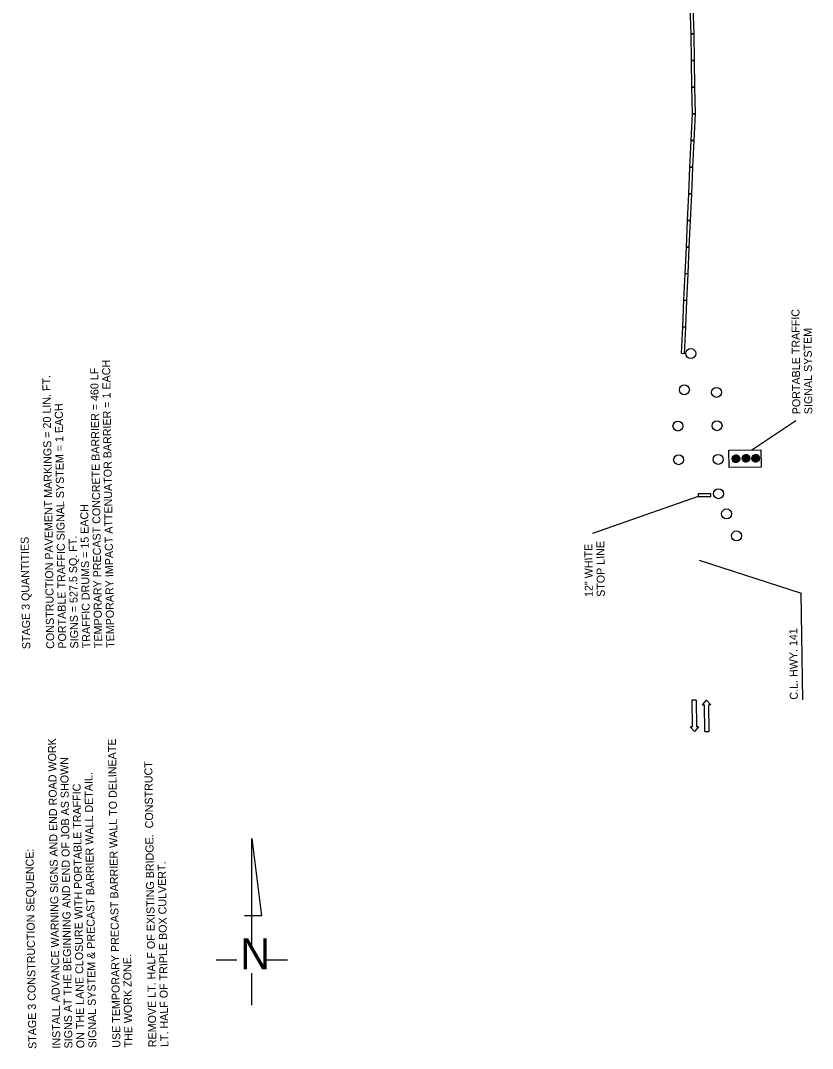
# Model space of a CAD drawing. Extents: x 1770269 to 1771406, y 724066 to 730989.
# Drawn here: x 1770318 to 1770912, y 724066 to 724837 of the extents above; entities that cross this region are included whole.
import ezdxf

# ---------------------------------------------------------------- set-up
doc = ezdxf.new("R2010")
doc.units = 0
for name, color, linetype in [('Default', 7, 'Continuous'), ('R_Border Notes', 7, 'Continuous'), ('R_Dimension', 7, 'Continuous'), ('R_Draft', 7, 'Continuous'), ('R_Horz Alg Annot', 7, 'Continuous'), ('R_MOT', 7, 'Continuous'), ('R_Striping', 7, 'Continuous'), ('T_Vehicle Path Rt', 7, 'Continuous')]:
    doc.layers.add(name, color=color, linetype=linetype)

msp = doc.modelspace()

# ---------------------------------------------------------------- linework, layer by layer
at = {"layer": 'Default'}
for p, q in [((1770854.8, 724505.27), (1770851.77, 724508.24)), ((1770854.63, 724505.26), (1770851.77, 724508.07)), ((1770854.97, 724505.28), (1770851.78, 724508.41)), ((1770854.44, 724505.27), (1770851.78, 724507.88)), ((1770855.12, 724505.3), (1770851.8, 724508.56)), ((1770854.24, 724505.29), (1770851.81, 724507.68)), ((1770855.27, 724505.33), (1770851.83, 724508.71)), ((1770854.02, 724505.33), (1770851.85, 724507.47)), ((1770855.41, 724505.37), (1770851.86, 724508.86)), ((1770855.55, 724505.41), (1770851.9, 724508.99)), ((1770853.78, 724505.39), (1770851.92, 724507.22)), ((1770855.68, 724505.45), (1770851.95, 724509.12)), ((1770855.81, 724505.51), (1770851.99, 724509.25)), ((1770853.49, 724505.5), (1770852.03, 724506.94)), ((1770855.93, 724505.56), (1770852.05, 724509.37)), ((1770856.04, 724505.62), (1770852.11, 724509.49)), ((1770856.15, 724505.69), (1770852.17, 724509.6)), ((1770856.26, 724505.76), (1770852.24, 724509.71)), ((1770853.1, 724505.71), (1770852.25, 724506.55)), ((1770856.37, 724505.83), (1770852.31, 724509.82)), ((1770856.46, 724505.91), (1770852.39, 724509.92)), ((1770856.56, 724505.99), (1770852.47, 724510.01)), ((1770856.65, 724506.08), (1770852.55, 724510.11)), ((1770856.74, 724506.17), (1770852.64, 724510.2)), ((1770856.82, 724506.26), (1770852.73, 724510.28)), ((1770856.9, 724506.36), (1770852.83, 724510.36)), ((1770856.98, 724506.46), (1770852.93, 724510.44)), ((1770857.05, 724506.56), (1770853.03, 724510.51)), ((1770857.12, 724506.67), (1770853.14, 724510.58)), ((1770857.18, 724506.78), (1770853.25, 724510.65)), ((1770857.24, 724506.9), (1770853.36, 724510.71)), ((1770857.3, 724507.02), (1770853.48, 724510.77)), ((1770857.34, 724507.15), (1770853.61, 724510.82)), ((1770857.39, 724507.28), (1770853.74, 724510.87)), ((1770857.43, 724507.42), (1770853.88, 724510.91)), ((1770857.46, 724507.56), (1770854.02, 724510.94)), ((1770857.49, 724507.71), (1770854.17, 724510.97)), ((1770857.51, 724507.87), (1770854.32, 724510.99)), ((1770857.52, 724508.03), (1770854.49, 724511.01)), ((1770857.52, 724508.2), (1770854.66, 724511.01)), ((1770857.51, 724508.39), (1770854.85, 724511)), ((1770857.48, 724508.59), (1770855.05, 724510.98)), ((1770857.44, 724508.81), (1770855.27, 724510.94)), ((1770857.37, 724509.05), (1770855.51, 724510.88)), ((1770857.26, 724509.34), (1770855.8, 724510.77)), ((1770857.04, 724509.73), (1770856.19, 724510.56)), ((1770862.29, 724505.6), (1770859.25, 724508.57)), ((1770862.11, 724505.59), (1770859.25, 724508.4)), ((1770861.93, 724505.6), (1770859.26, 724508.21)), ((1770862.45, 724505.61), (1770859.27, 724508.74)), ((1770862.61, 724505.63), (1770859.28, 724508.89)), ((1770861.73, 724505.62), (1770859.29, 724508.01)), ((1770862.75, 724505.66), (1770859.31, 724509.04)), ((1770861.51, 724505.66), (1770859.33, 724507.8)), ((1770862.9, 724505.7), (1770859.34, 724509.19)), ((1770863.03, 724505.74), (1770859.38, 724509.32)), ((1770861.26, 724505.72), (1770859.4, 724507.55)), ((1770863.16, 724505.78), (1770859.43, 724509.45)), ((1770863.29, 724505.84), (1770859.48, 724509.58)), ((1770860.97, 724505.83), (1770859.52, 724507.27)), ((1770863.41, 724505.89), (1770859.53, 724509.7)), ((1770863.53, 724505.95), (1770859.59, 724509.82)), ((1770863.64, 724506.02), (1770859.65, 724509.93)), ((1770863.74, 724506.09), (1770859.72, 724510.04)), ((1770860.58, 724506.04), (1770859.73, 724506.88)), ((1770863.85, 724506.16), (1770859.79, 724510.15)), ((1770863.95, 724506.24), (1770859.87, 724510.25)), ((1770864.04, 724506.32), (1770859.95, 724510.34)), ((1770864.13, 724506.41), (1770860.03, 724510.44)), ((1770864.22, 724506.5), (1770860.12, 724510.52)), ((1770864.31, 724506.59), (1770860.21, 724510.61)), ((1770864.39, 724506.69), (1770860.31, 724510.69)), ((1770864.46, 724506.79), (1770860.41, 724510.77)), ((1770864.53, 724506.89), (1770860.51, 724510.84)), ((1770864.6, 724507), (1770860.62, 724510.91)), ((1770864.66, 724507.11), (1770860.73, 724510.98)), ((1770864.72, 724507.23), (1770860.85, 724511.04)), ((1770864.78, 724507.35), (1770860.97, 724511.1)), ((1770864.83, 724507.48), (1770861.09, 724511.15)), ((1770864.87, 724507.61), (1770861.22, 724511.19)), ((1770864.91, 724507.75), (1770861.36, 724511.24)), ((1770864.94, 724507.89), (1770861.5, 724511.27)), ((1770864.97, 724508.04), (1770861.65, 724511.3)), ((1770864.99, 724508.2), (1770861.81, 724511.32)), ((1770865, 724508.36), (1770861.97, 724511.34)), ((1770865, 724508.53), (1770862.15, 724511.34)), ((1770864.99, 724508.72), (1770862.33, 724511.33)), ((1770864.97, 724508.92), (1770862.53, 724511.31)), ((1770864.92, 724509.14), (1770862.75, 724511.27)), ((1770864.85, 724509.38), (1770862.99, 724511.21)), ((1770864.74, 724509.67), (1770863.28, 724511.1)), ((1770864.52, 724510.06), (1770863.68, 724510.89)), ((1770869.46, 724505.66), (1770866.52, 724508.54)), ((1770869.63, 724505.66), (1770866.53, 724508.71)), ((1770869.28, 724505.66), (1770866.53, 724508.36)), ((1770869.79, 724505.68), (1770866.54, 724508.87)), ((1770869.09, 724505.67), (1770866.55, 724508.17)), ((1770869.94, 724505.71), (1770866.57, 724509.02)), ((1770868.88, 724505.7), (1770866.58, 724507.96)), ((1770870.09, 724505.74), (1770866.59, 724509.17)), ((1770870.23, 724505.78), (1770866.63, 724509.31)), ((1770868.64, 724505.76), (1770866.64, 724507.73)), ((1770870.36, 724505.82), (1770866.67, 724509.45)), ((1770870.49, 724505.87), (1770866.72, 724509.57)), ((1770868.38, 724505.84), (1770866.73, 724507.46)), ((1770870.61, 724505.92), (1770866.77, 724509.7)), ((1770870.73, 724505.98), (1770866.83, 724509.82)), ((1770868.05, 724505.99), (1770866.88, 724507.14)), ((1770870.85, 724506.05), (1770866.89, 724509.93)), ((1770870.95, 724506.11), (1770866.95, 724510.04)), ((1770871.06, 724506.19), (1770867.02, 724510.15)), ((1770871.16, 724506.26), (1770867.1, 724510.25)), ((1770871.26, 724506.34), (1770867.17, 724510.35)), ((1770871.35, 724506.42), (1770867.26, 724510.45)), ((1770871.44, 724506.51), (1770867.34, 724510.54)), ((1770871.53, 724506.6), (1770867.43, 724510.63)), ((1770871.61, 724506.7), (1770867.52, 724510.71)), ((1770871.69, 724506.79), (1770867.62, 724510.79)), ((1770871.76, 724506.9), (1770867.72, 724510.87)), ((1770871.83, 724507), (1770867.83, 724510.94)), ((1770871.9, 724507.11), (1770867.94, 724511.01)), ((1770871.96, 724507.23), (1770868.05, 724511.07)), ((1770872.02, 724507.35), (1770868.17, 724511.13)), ((1770872.12, 724507.6), (1770868.42, 724511.23)), ((1770872.16, 724507.73), (1770868.55, 724511.28)), ((1770872.2, 724507.87), (1770868.69, 724511.32)), ((1770872.23, 724508.02), (1770868.84, 724511.35)), ((1770872.25, 724508.17), (1770868.99, 724511.38)), ((1770872.26, 724508.33), (1770869.15, 724511.39)), ((1770872.27, 724508.5), (1770869.32, 724511.4)), ((1770872.27, 724508.68), (1770869.5, 724511.4)), ((1770872.25, 724508.87), (1770869.69, 724511.39)), ((1770872.22, 724509.08), (1770869.89, 724511.36)), ((1770872.17, 724509.31), (1770870.12, 724511.31)), ((1770872.08, 724509.57), (1770870.39, 724511.23)), ((1770871.93, 724509.88), (1770870.71, 724511.09)), ((1770871.54, 724510.44), (1770871.27, 724510.71)), ((1770827.13, 724432.18), (1770903.59, 724407.46)), ((1770904.82, 724327.29), (1770903.59, 724407.46))]:
    msp.add_line(p, q, dxfattribs=at)
msp.add_lwpolyline([(1770849.47, 724501.66), (1770849.36, 724514.65), (1770873.33, 724514.87), (1770873.45, 724501.88)], close=True, dxfattribs=at)
for centre in [(1770854.64, 724508.14), (1770862.13, 724508.47), (1770869.4, 724508.53)]:
    msp.add_circle(centre, 2.87, dxfattribs=at)
at = {"layer": 'R_Border Notes'}
for p, q in [((1770824.76, 724327.24), (1770821.56, 724327.19)), ((1770821.56, 724327.19), (1770821.87, 724307.21)), ((1770824.76, 724327.24), (1770825.07, 724307.25)), ((1770829.51, 724323.63), (1770832.65, 724327.19)), ((1770829.51, 724323.63), (1770831.11, 724323.66)), ((1770831.41, 724303.68), (1770831.11, 724323.66)), ((1770832.65, 724327.19), (1770835.91, 724323.73)), ((1770835.91, 724323.73), (1770834.31, 724323.71)), ((1770834.61, 724303.73), (1770834.31, 724323.71)), ((1770820.27, 724307.18), (1770821.87, 724307.21)), ((1770823.52, 724303.72), (1770820.27, 724307.18)), ((1770826.67, 724307.28), (1770823.52, 724303.72)), ((1770826.67, 724307.28), (1770825.07, 724307.25)), ((1770831.41, 724303.68), (1770834.61, 724303.73))]:
    msp.add_line(p, q, dxfattribs=at)
at = {"layer": 'R_Dimension'}
for p, q in [((1770866.59, 724514.81), (1770899.46, 724536.9)), ((1770826.4, 724479.75), (1770746.99, 724452.05))]:
    msp.add_line(p, q, dxfattribs=at)
at = {"layer": 'R_Draft'}
for p, q in [((1770491.63, 724223.55), (1770498.91, 724165.36)), ((1770491.63, 724142.19), (1770491.63, 724223.55)), ((1770485.98, 724165.79), (1770498.92, 724165.79)), ((1770464.87, 724132.6), (1770480.3, 724132.6)), ((1770501.9, 724132.6), (1770518.38, 724132.6)), ((1770491.63, 724098.55), (1770491.63, 724122.47))]:
    msp.add_line(p, q, dxfattribs=at)
at = {"layer": 'R_MOT'}
for centre in [(1770820.73, 724587.02), (1770815.94, 724559.85), (1770840.11, 724557.92), (1770811.14, 724532.67), (1770840.45, 724532.93), (1770811.65, 724507.42), (1770841.33, 724507.68), (1770841.58, 724481.96), (1770847.63, 724466.81), (1770855.09, 724450.32)]:
    msp.add_circle(centre, 3.75, dxfattribs=at)
at = {"layer": 'R_Striping'}
for p, q in [((1770835.73, 724481.9), (1770826.37, 724481.75)), ((1770826.37, 724481.75), (1770826.4, 724479.75)), ((1770826.4, 724479.75), (1770835.76, 724479.9)), ((1770835.76, 724479.9), (1770835.73, 724481.9))]:
    msp.add_line(p, q, dxfattribs=at)
for points in [[(1770835.73, 724481.9), (1770835.73, 724481.9)], [(1770835.76, 724479.9), (1770835.76, 724479.9)]]:
    msp.add_lwpolyline(points, dxfattribs=at)
at = {"layer": 'T_Vehicle Path Rt'}
for points in [[(1770820.99, 724826.65), (1770820.35, 724846.64), (1770822.35, 724846.7), (1770822.99, 724826.71)], [(1770821.33, 724806.65), (1770820.99, 724826.65), (1770822.99, 724826.68), (1770823.33, 724806.68)], [(1770821.67, 724786.65), (1770821.33, 724806.65), (1770823.33, 724806.68), (1770823.67, 724786.69)], [(1770822.01, 724766.66), (1770821.67, 724786.65), (1770823.67, 724786.69), (1770824.01, 724766.69)], [(1770821.1, 724746.8), (1770822.02, 724766.78), (1770824.01, 724766.69), (1770823.1, 724746.71)], [(1770820.18, 724726.82), (1770821.1, 724746.8), (1770823.1, 724746.71), (1770822.18, 724726.73)], [(1770819.27, 724706.85), (1770820.18, 724726.82), (1770822.18, 724726.73), (1770821.27, 724706.75)], [(1770818.35, 724686.87), (1770819.27, 724706.85), (1770821.27, 724706.75), (1770820.35, 724686.77)], [(1770817.44, 724666.89), (1770818.35, 724686.87), (1770820.35, 724686.77), (1770819.43, 724666.8)], [(1770816.52, 724646.91), (1770817.44, 724666.89), (1770819.43, 724666.8), (1770818.52, 724646.82)], [(1770815.6, 724626.93), (1770816.52, 724646.91), (1770818.52, 724646.82), (1770817.6, 724626.84)], [(1770814.69, 724606.95), (1770815.6, 724626.93), (1770817.6, 724626.84), (1770816.69, 724606.86)], [(1770813.77, 724586.97), (1770814.69, 724606.95), (1770816.69, 724606.86), (1770815.77, 724586.88)]]:
    msp.add_lwpolyline(points, close=True, dxfattribs=at)

# ---------------------------------------------------------------- texts
at = {"layer": 'R_Dimension'}
for s, p in [('PORTABLE TRAFFIC', (1770902.93, 724541.52)), ('SIGNAL SYSTEM', (1770911.93, 724541.6)), ('STOP LINE', (1770756.3, 724404.62)), ('12" WHITE', (1770747.3, 724404.54))]:
    msp.add_text(s, height=6, rotation=90.50571, dxfattribs=at).set_placement(p)
at = {"layer": 'R_Draft'}
for s, p in [('TEMPORARY PRECAST CONCRETE BARRIER = 460 LF', (1770379.45, 724366.25)), ('TEMPORARY IMPACT ATTENUATOR BARRIER = 1 EACH', (1770388.45, 724366.38)), ('CONSTRUCTION PAVEMENT MARKINGS = 20 LIN. FT.', (1770343.45, 724365.72)), ('PORTABLE TRAFFIC SIGNAL SYSTEM = 1 EACH', (1770352.45, 724365.85)), ('TRAFFIC DRUMS = 15 EACH', (1770370.45, 724366.11)), ('STAGE 3 QUANTITIES', (1770325.45, 724365.45)), ('SIGNS = 527.5 SQ. FT.', (1770361.45, 724365.98)), ('INSTALL ADVANCE WARNING SIGNS AND END ROAD WORK ', (1770348.07, 724065.98)), ('USE TEMPORARY PRECAST BARRIER WALL TO DELINEATE', (1770393.06, 724066.64)), ('SIGNS AT THE BEGINNING AND END OF JOB AS SHOWN ', (1770357.07, 724066.11)), ('REMOVE LT. HALF OF EXISTING BRIDGE.  CONSTRUCT', (1770420.06, 724067.04)), ('SIGNAL SYSTEM & PRECAST BARRIER WALL DETAIL.', (1770375.07, 724066.38)), ('ON THE LANE CLOSURE WITH PORTABLE TRAFFIC ', (1770366.07, 724066.24)), ('STAGE 3 CONSTRUCTION SEQUENCE:', (1770330.07, 724065.71)), ('LT. HALF OF TRIPLE BOX CULVERT. ', (1770429.06, 724067.18)), ('THE WORK ZONE. ', (1770402.06, 724066.78))]:
    msp.add_text(s, height=6, rotation=90.84663, dxfattribs=at).set_placement(p)
msp.add_text('N', height=23.27, dxfattribs=at).set_placement((1770482.8, 724125.44))
at = {"layer": 'R_Horz Alg Annot'}
msp.add_text('C.L. HWY. 141', height=6, rotation=90.50367, dxfattribs=at).set_placement((1770901.05, 724327.59))

doc.saveas('drawing.dxf')
